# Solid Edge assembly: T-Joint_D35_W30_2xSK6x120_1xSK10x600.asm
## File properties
Author: fknapp
Template: iso metric assembly.asm
Last saved by: fknapp
Revision: 16
Application: Solid Edge
Username: fknapp
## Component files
T-Joint_D35_W30.par
SK Schraube 10x600_ohne_Gewinde_22042020.par
SK Schraube 6x120_ohne_Gewinde.par
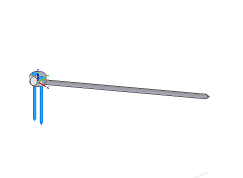
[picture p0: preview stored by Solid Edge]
